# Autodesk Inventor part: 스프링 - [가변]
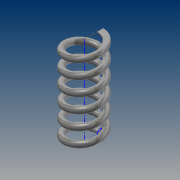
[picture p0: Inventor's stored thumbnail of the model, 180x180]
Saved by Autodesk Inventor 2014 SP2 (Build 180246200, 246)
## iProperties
Created: 2015-12
Part Number: 스프링 - [가변]
Material: 강철, 탄소
Document SubType Name: Modeling
Designer: Administrator
Mass: 16.5345 g
Surface Area: 28.5107 cm^2
Volume: 2.10095 cm^3
Density: 7.87 g/cm^3
Appearance: 반연마
Author: Administrator
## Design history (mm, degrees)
sketch "스케치2"
  geometry: L1 (0, 0)-(8, 0); L2 (8, 0)-(8, 42); L3 (8, 42)-(0, 42); L4 (0, 42)-(0, 0); C1 r 1.5 at (8, 0)
  constraints: 8 end point, 2 parallel, 1 centre point, 1 coincident, 1 horizontal, 1 perpendicular
  dimensions: "d2" = 16 diameter of L2 L4; "d3" = 42 distance of L1.end L2.end (derived); "d4" = 3 diameter of C1
feature "코일1" sketch "스케치2" pitch "d5" = 10; turns "d7" = 6; dims "d6" = 41.99992 (computed from d3), "d8" = 0, angle "d9" = 90 deg, angle "d10" = 90 deg, "d11" = 0, "d12" = 0
node "작업 평면1"
feature "분할1"
feature "분할2"
node "솔리드1"
other parameters: "d13" = 0
